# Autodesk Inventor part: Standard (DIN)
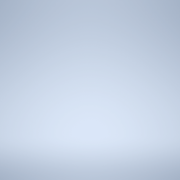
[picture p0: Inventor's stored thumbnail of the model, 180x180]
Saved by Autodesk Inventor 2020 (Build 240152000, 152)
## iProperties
Created: 2019-02
Part Number: Standard (DIN)
Material: Ogólny
Document SubType Name: Modeling
Density: 1 g/cm^3
Appearance: Domyślna
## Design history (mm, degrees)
